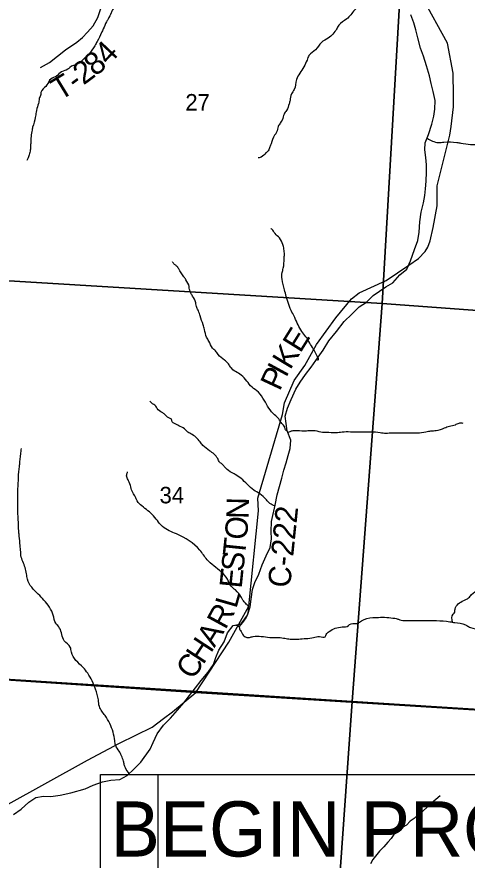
# Model space of a CAD drawing. Extents: x -13.1 to 43.1, y 0 to 22.
# Drawn here: x 3.976 to 5.119, y 16.632 to 18.772 of the extents above; entities that cross this region are included whole.
import ezdxf

# ---------------------------------------------------------------- set-up
doc = ezdxf.new("R2010")
doc.units = 0
for name, color, linetype in [('GM_X_Corporation', 7, 'Continuous'), ('GM_X_County_Road', 7, 'Continuous'), ('GM_X_County_Road_Text', 7, 'Continuous'), ('GM_X_Minor_River', 7, 'Continuous'), ('GM_X_Section_Text', 7, 'Continuous'), ('GM_X_Township_Road', 7, 'Continuous'), ('GM_X_Township_Road_Text', 7, 'Continuous'), ('SH_Masking', 7, 'Continuous'), ('SH_Text', 7, 'Continuous')]:
    doc.layers.add(name, color=color, linetype=linetype)

msp = doc.modelspace()

# ---------------------------------------------------------------- linework, layer by layer
at = {"layer": 'GM_X_Corporation'}
for points in [[(7.0804, 20.9), (2.1, 20.9), (2.1, 17.2152), (2.1437, 17.2135), (2.8442, 17.1637), (3.8328, 17.0966), (4.4304, 17.0575), (6.8234, 16.908), (6.8365, 17.1257), (6.9507, 19.0184), (6.9616, 19.1692), (7.0106, 19.8452), (7.0162, 19.896), (7.0615, 20.6138)], [(3.9684, 19.0905), (4.9602, 19.0234), (4.9031, 18.044), (3.9134, 18.1046)], [(4.9602, 19.0234), (5.9495, 18.9594), (5.8912, 17.9717), (4.9031, 18.044)], [(4.9031, 18.044), (4.8272, 17.0344), (3.8395, 17.0976), (3.9134, 18.1046)], [(4.9031, 18.044), (5.8912, 17.9717), (5.8169, 16.9715), (4.8272, 17.0344)], [(2.1, 17.2152), (2.1, 14.1), (6.619, 14.1), (6.6992, 15.2074), (6.7528, 15.9566), (6.8234, 16.908), (4.4304, 17.0575), (3.8328, 17.0966), (2.8442, 17.1637), (2.1437, 17.2135)], [(3.8395, 17.0976), (4.8272, 17.0344), (4.7589, 16.0643), (3.7693, 16.1222)], [(4.8272, 17.0344), (5.8169, 16.9715), (5.7391, 16.0144), (4.7589, 16.0643)]]:
    msp.add_lwpolyline(points, close=True, dxfattribs=at)
at = {"layer": 'GM_X_County_Road'}
for points in [[(5.0783, 18.4932), (5.0848, 18.5434), (5.0843, 18.5717), (5.0834, 18.6291), (5.0689, 18.7047), (5.0057, 18.8205)], [(4.348, 16.991), (4.3711, 17.0083), (4.4306, 17.0569), (4.5145, 17.185), (4.5648, 17.2761), (4.5898, 17.5185), (4.5882, 17.5504), (4.6501, 17.7629), (4.6558, 17.7923), (4.6802, 17.8489), (4.7075, 17.887), (4.7367, 17.9403), (4.7858, 18.0078), (4.8257, 18.056), (4.8449, 18.0712), (4.9135, 18.1029), (4.9707, 18.1417), (4.996, 18.1588), (5.0124, 18.1761), (5.0195, 18.1874), (5.0253, 18.2031), (5.0327, 18.2373), (5.0429, 18.2924), (5.0432, 18.3425), (5.0754, 18.4715), (5.0783, 18.4932)], [(3.7439, 16.658), (4.1556, 16.8859), (4.2369, 16.929), (4.3192, 16.9696), (4.348, 16.991)]]:
    msp.add_lwpolyline(points, dxfattribs=at)
at = {"layer": 'GM_X_Minor_River'}
for points in [[(4.7413, 17.9083), (4.7535, 17.9256), (4.7681, 17.9498), (4.7872, 17.9731), (4.8071, 17.9988), (4.8262, 18.0176), (4.8453, 18.0356), (4.8635, 18.0476), (4.8803, 18.0649), (4.9131, 18.0867), (4.9306, 18.0971), (4.9481, 18.1167), (4.9664, 18.131), (4.9757, 18.1529), (4.9858, 18.1809), (4.9943, 18.2044), (4.9975, 18.2256), (4.9992, 18.2514), (5.0024, 18.2764), (5.0079, 18.2998), (5.0119, 18.318), (5.0135, 18.3355), (5.0152, 18.3544), (5.0161, 18.3772), (5.0163, 18.3961), (5.0142, 18.4151), (5.0113, 18.4341), (5.0129, 18.4516), (5.0214, 18.4727), (5.0292, 18.4992), (5.0347, 18.5197), (5.0371, 18.5371), (5.038, 18.5591), (5.0329, 18.5819), (5.0278, 18.6024), (5.0234, 18.6222), (5.016, 18.6473), (5.0087, 18.6716), (5.0005, 18.6922), (4.9939, 18.718), (4.9888, 18.7386), (4.9836, 18.7568), (4.9762, 18.7766)], [(3.968, 16.7477), (3.987, 16.7612), (4.0061, 16.7792), (4.0244, 16.7912), (4.0441, 16.7941), (4.0622, 16.7932), (4.0857, 16.7968), (4.113, 16.8026), (4.1494, 16.8129), (4.17, 16.8219), (4.1935, 16.8308), (4.2147, 16.8352), (4.2375, 16.8365), (4.2565, 16.847), (4.274, 16.8635), (4.2908, 16.8808), (4.3145, 16.9132), (4.3223, 16.9306), (4.3323, 16.9526), (4.3484, 16.9744), (4.3659, 16.9917), (4.3835, 17.0121), (4.4003, 17.0309), (4.4141, 17.0498), (4.4294, 17.0694), (4.4439, 17.0875), (4.4615, 17.1086), (4.4753, 17.1282), (4.4815, 17.1463), (4.4892, 17.1645), (4.5022, 17.1856), (4.5108, 17.2083), (4.5253, 17.2272), (4.5458, 17.2315), (4.5618, 17.2534), (4.5681, 17.2746), (4.5705, 17.2943), (4.5745, 17.3186), (4.5799, 17.336), (4.5907, 17.3579), (4.5985, 17.3813), (4.6092, 17.404), (4.6193, 17.4252), (4.6225, 17.4472), (4.6219, 17.4654), (4.6228, 17.4912), (4.6315, 17.5328), (4.637, 17.5586), (4.6425, 17.5798), (4.6487, 17.601), (4.6542, 17.6214), (4.6596, 17.6396), (4.6651, 17.6585), (4.6698, 17.6767), (4.6714, 17.6979), (4.6625, 17.7215), (4.6575, 17.7587), (4.663, 17.7784), (4.6723, 17.8011), (4.6846, 17.8268), (4.6953, 17.8449), (4.7084, 17.8638), (4.7229, 17.8826), (4.7413, 17.9083)], [(5.0502, 16.7954), (5.0394, 16.7854), (5.029, 16.7765), (5.0187, 16.7672), (5.0068, 16.756), (4.996, 16.7475), (4.9849, 16.7378), (4.9746, 16.7304), (4.9653, 16.7203), (4.9543, 16.7148), (4.9443, 16.7051), (4.9332, 16.6966), (4.9262, 16.6869), (4.9174, 16.6772), (4.9077, 16.6656), (4.8966, 16.6548), (4.8796, 16.6338), (4.8737, 16.6229)]]:
    msp.add_lwpolyline(points, dxfattribs=at)
for points in [[(4.8375, 19.0235), (4.8415, 19.0229), (4.8385, 19.0177), (4.8294, 19.0125), (4.815, 19.0097), (4.8105, 19.0105), (4.8034, 19.0155), (4.7981, 19.019), (4.7819, 19.0279), (4.7714, 19.0341), (4.7549, 19.0487), (4.7474, 19.0564), (4.7366, 19.0747), (4.7317, 19.0842), (4.722, 19.1002), (4.7176, 19.1075), (4.7082, 19.1212), (4.703, 19.1285), (4.6902, 19.143), (4.6655, 19.1631), (4.661, 19.1714), (4.652, 19.1814), (4.6291, 19.195), (4.6182, 19.1989), (4.6008, 19.2033), (4.5937, 19.2049), (4.5823, 19.2058), (4.5767, 19.2059), (4.5653, 19.2049), (4.5601, 19.2046), (4.5551, 19.2043), (4.5487, 19.2037), (4.5397, 19.2038), (4.537, 19.2031), (4.5306, 19.2017), (4.5261, 19.2006), (4.5143, 19.1992), (4.5072, 19.199), (4.4939, 19.1965), (4.4886, 19.1947), (4.4818, 19.1891), (4.478, 19.185), (4.4708, 19.1787), (4.4674, 19.1753), (4.4639, 19.172), (4.4552, 19.1615), (4.451, 19.1551), (4.443, 19.1424), (4.4399, 19.1349), (4.4356, 19.1172), (4.4325, 19.1036), (4.4283, 19.0938), (4.418, 19.0724), (4.4054, 19.0545), (4.3996, 19.044), (4.3973, 19.0323), (4.3821, 19.0166), (4.3679, 18.9915), (4.3595, 18.9783), (4.3409, 18.9533), (4.3306, 18.9425), (4.3135, 18.9212), (4.3039, 18.9096), (4.2834, 18.8894), (4.2751, 18.8801), (4.2602, 18.8633), (4.2537, 18.8558), (4.2449, 18.8401), (4.2407, 18.8311), (4.2312, 18.8127), (4.2266, 18.8044), (4.2193, 18.7894), (4.2155, 18.7819), (4.2078, 18.7661), (4.2036, 18.7586), (4.1956, 18.7413), (4.191, 18.7316), (4.1802, 18.7094), (4.1738, 18.6985), (4.1585, 18.6768), (4.1479, 18.6671), (4.1293, 18.6515), (4.1107, 18.6435), (4.1054, 18.6386), (4.0895, 18.6324), (4.0766, 18.6209), (4.0622, 18.6139), (4.0526, 18.5989), (4.0397, 18.5851), (4.037, 18.5776), (4.0362, 18.5723), (4.0339, 18.567), (4.0316, 18.555), (4.0296, 18.5478), (4.025, 18.5294), (4.023, 18.5165), (4.016, 18.492)], [(4.9331, 18.8445), (4.9369, 18.8404), (4.9233, 18.8289), (4.8968, 18.8191), (4.874, 18.8096), (4.8434, 18.7968), (4.8335, 18.7886), (4.8133, 18.7662), (4.7932, 18.7506), (4.7875, 18.7408), (4.7666, 18.7177), (4.7491, 18.7066), (4.7343, 18.6883), (4.7176, 18.6738), (4.7126, 18.6621), (4.6946, 18.6287), (4.6858, 18.6126), (4.68, 18.587), (4.6731, 18.5765), (4.6696, 18.5595), (4.6673, 18.5508), (4.6604, 18.5339), (4.6543, 18.5249), (4.6523, 18.5182), (4.6447, 18.502), (4.6393, 18.4934), (4.6354, 18.4791), (4.6305, 18.4712), (4.6213, 18.4498), (4.6182, 18.4415), (4.614, 18.4317), (4.6083, 18.4265), (4.5965, 18.4157), (4.5912, 18.4143), (4.5886, 18.4143)], [(4.016, 18.492), (4.0141, 18.4811), (4.0117, 18.4641), (4.0113, 18.4562), (4.0112, 18.4505), (4.0108, 18.4407), (4.0104, 18.4358), (4.0096, 18.4305), (4.0068, 18.4188), (4.0049, 18.4139), (4.0015, 18.4068)], [(5.0177, 18.4635), (5.0456, 18.4528), (5.06, 18.4538), (5.0928, 18.4529), (5.1034, 18.4512), (5.1275, 18.4479), (5.1494, 18.4472), (5.1573, 18.444), (5.1715, 18.431), (5.1794, 18.4192), (5.182, 18.4085), (5.1912, 18.3774), (5.2035, 18.3564), (5.2091, 18.3439), (5.227, 18.3194), (5.2378, 18.3026), (5.2412, 18.2908), (5.2515, 18.2586), (5.2567, 18.2384), (5.2645, 18.2262), (5.2775, 18.1984), (5.2861, 18.1817), (5.2887, 18.1714), (5.2956, 18.1452), (5.3001, 18.1308), (5.3008, 18.1229), (5.3043, 18.0876), (5.305, 18.0789), (5.3071, 18.0558), (5.3093, 18.0433), (5.3107, 18.0361), (5.3148, 18.0179), (5.3173, 18.0065), (5.3267, 17.9905), (5.3285, 17.9799), (5.3326, 17.9723), (5.3411, 17.9536), (5.3471, 17.9437), (5.3569, 17.9375), (5.3722, 17.9226), (5.3801, 17.9141), (5.3906, 17.9095), (5.4042, 17.8983), (5.4121, 17.8933), (5.4237, 17.8916), (5.4419, 17.8898), (5.4502, 17.8916), (5.4649, 17.8936), (5.488, 17.8971), (5.4967, 17.9), (5.5069, 17.9017), (5.5194, 17.9088), (5.5285, 17.9166), (5.5463, 17.9224), (5.5769, 17.9355), (5.5868, 17.9362), (5.5913, 17.9372)], [(4.7367, 17.9019), (4.7413, 17.9013), (4.7398, 17.9081), (4.7361, 17.9161), (4.7197, 17.9436), (4.71, 17.96), (4.6995, 17.973), (4.6816, 18.0084), (4.6745, 18.0221), (4.6601, 18.0617), (4.6553, 18.0787), (4.6495, 18.106), (4.6496, 18.1231), (4.6523, 18.1336), (4.6547, 18.1585), (4.6552, 18.1691), (4.6541, 18.1824), (4.6531, 18.1888), (4.6512, 18.1937), (4.6426, 18.2109), (4.6314, 18.2216), (4.6235, 18.2327), (4.6205, 18.2343)], [(4.6625, 17.7215), (4.6581, 17.7236), (4.6563, 17.7308), (4.6488, 17.7396), (4.641, 17.7515), (4.6305, 17.7615), (4.6039, 17.7989), (4.5893, 17.8191), (4.5732, 17.8322), (4.5458, 17.8625), (4.5188, 17.8822), (4.5132, 17.8913), (4.5031, 17.9005), (4.4873, 17.9147), (4.4802, 17.9243), (4.4727, 17.9308), (4.4634, 17.9491), (4.4578, 17.9587), (4.4526, 17.9784), (4.449, 17.9905), (4.4412, 18.0126), (4.4371, 18.0255), (4.433, 18.0339), (4.4301, 18.0464), (4.4223, 18.0631), (4.4197, 18.0673), (4.4163, 18.0738), (4.4156, 18.0769), (4.4145, 18.0799), (4.4134, 18.0871), (4.4052, 18.1046), (4.4, 18.1122), (4.3869, 18.1325), (4.3817, 18.1393), (4.3764, 18.1436), (4.3708, 18.1497)], [(4.631, 17.5306), (4.6183, 17.537), (4.6135, 17.5416), (4.6097, 17.5462), (4.5925, 17.5616), (4.5778, 17.5709), (4.5452, 17.6001), (4.5305, 17.6105), (4.5177, 17.6175), (4.5027, 17.6306), (4.4971, 17.6367), (4.4907, 17.6417), (4.4859, 17.6508), (4.4652, 17.6708), (4.4483, 17.6839), (4.4412, 17.6931), (4.418, 17.7138), (4.4082, 17.7196), (4.4018, 17.7265), (4.3872, 17.7339), (4.383, 17.7366), (4.3706, 17.7444), (4.3688, 17.7501), (4.3616, 17.7539), (4.3511, 17.7635), (4.3451, 17.7674), (4.3323, 17.7778), (4.3305, 17.7816), (4.3207, 17.7897), (4.3136, 17.7966)], [(4.664, 17.7176), (4.6698, 17.7197), (4.6732, 17.7208), (4.6819, 17.7222), (4.7049, 17.7211), (4.7178, 17.722), (4.7329, 17.7218), (4.7521, 17.7178), (4.7615, 17.7176), (4.7861, 17.7169), (4.8016, 17.7186), (4.8227, 17.719), (4.8593, 17.7185), (4.874, 17.719), (4.8982, 17.7172), (4.9057, 17.7159), (4.9208, 17.7157), (4.9454, 17.7158), (4.9574, 17.716), (4.9888, 17.7163), (4.9926, 17.7162), (5.0145, 17.7189), (5.0273, 17.721), (5.0402, 17.722), (5.0617, 17.7285), (5.0742, 17.7332), (5.0893, 17.7368), (5.0984, 17.7408), (5.1082, 17.741)], [(4.2611, 16.8513), (4.2516, 16.8658), (4.2487, 16.8738), (4.2469, 16.8832), (4.2417, 16.8969), (4.2357, 16.9083), (4.2268, 16.9232), (4.2246, 16.935), (4.2202, 16.9566), (4.2001, 16.9985), (4.1855, 17.0217), (4.183, 17.0384), (4.176, 17.0654), (4.1559, 17.1061), (4.1443, 17.1206), (4.1144, 17.1596), (4.1118, 17.1725), (4.0965, 17.1883), (4.0846, 17.2209), (4.0749, 17.2328), (4.0686, 17.2533), (4.0447, 17.2918), (4.0305, 17.3068), (4.0028, 17.3446), (4.0006, 17.3586), (3.9914, 17.3894), (3.9866, 17.4046), (3.9859, 17.4144), (3.9845, 17.43), (3.9824, 17.4542), (3.9813, 17.464), (3.9803, 17.4811), (3.979, 17.511), (3.9787, 17.5215), (3.9785, 17.5367), (3.9787, 17.5749), (3.98, 17.5941), (3.98, 17.6028), (3.9829, 17.6308), (3.9837, 17.6425), (3.9869, 17.6704), (3.9877, 17.6761)], [(5.0816, 17.2356), (5.0834, 17.2559), (5.0864, 17.2589), (5.0884, 17.2687), (5.1104, 17.2907), (5.1229, 17.2973), (5.1305, 17.3059), (5.1483, 17.3185), (5.1559, 17.3229), (5.1707, 17.3371), (5.1818, 17.3456), (5.1932, 17.3636), (5.2274, 17.3922), (5.2418, 17.4019), (5.2513, 17.4161), (5.2786, 17.4338), (5.2919, 17.4405), (5.3029, 17.4524), (5.3355, 17.4724), (5.3511, 17.4793), (5.3715, 17.493), (5.3768, 17.4967), (5.3818, 17.4997), (5.3951, 17.5135), (5.4049, 17.5202), (5.4136, 17.5242), (5.419, 17.5279), (5.4246, 17.5282), (5.4284, 17.5338), (5.4455, 17.5385), (5.4651, 17.545), (5.4708, 17.548), (5.4852, 17.5508), (5.4882, 17.5534), (5.5117, 17.5598), (5.5336, 17.5648), (5.5416, 17.5689), (5.5514, 17.5755), (5.5753, 17.5858), (5.5825, 17.588), (5.587, 17.5894), (5.5908, 17.5969), (5.5985, 17.6085), (5.6117, 17.6182), (5.6213, 17.632), (5.6357, 17.639)], [(4.5403, 17.2239), (4.5644, 17.2723), (4.5633, 17.2765), (4.5603, 17.2796), (4.5569, 17.2838), (4.5498, 17.2915), (4.5461, 17.2979), (4.5307, 17.3174), (4.5202, 17.3274), (4.5105, 17.345), (4.476, 17.3783), (4.4592, 17.3941), (4.4408, 17.4185), (4.3811, 17.4595), (4.3461, 17.4781), (4.336, 17.4892), (4.3229, 17.5053), (4.2933, 17.5307), (4.2816, 17.5433), (4.2783, 17.5509), (4.2671, 17.5715), (4.2657, 17.5787), (4.2597, 17.5947), (4.2571, 17.5996), (4.2549, 17.6095), (4.2565, 17.614), (4.2569, 17.617)], [(4.5307, 17.2283), (4.5403, 17.2239), (4.541, 17.2213), (4.5425, 17.2163), (4.5455, 17.2121), (4.5485, 17.2056), (4.5582, 17.1976), (4.5665, 17.1971), (4.5756, 17.1992), (4.6179, 17.1971), (4.6533, 17.1955), (4.6597, 17.1942), (4.6737, 17.1925), (4.7096, 17.1943), (4.7292, 17.1966), (4.744, 17.1991), (4.7591, 17.1989), (4.7614, 17.2045), (4.769, 17.2123), (4.8019, 17.2236), (4.8178, 17.2271), (4.8204, 17.2298), (4.8389, 17.2325), (4.8458, 17.2358), (4.8511, 17.2391), (4.8794, 17.2474), (4.8991, 17.2483), (4.9017, 17.2486), (4.9097, 17.2485), (4.9304, 17.246), (4.9413, 17.2443), (4.9481, 17.2415), (4.9632, 17.2398), (4.976, 17.24), (5.0089, 17.2403), (5.0417, 17.2398), (5.0753, 17.2367), (5.0874, 17.2346), (5.1149, 17.2293), (5.1186, 17.227), (5.1273, 17.2224), (5.151, 17.2118), (5.154, 17.2065), (5.1619, 17.1977), (5.1863, 17.1829), (5.1998, 17.1771), (5.2096, 17.1682), (5.2404, 17.1531), (5.2604, 17.1456), (5.2641, 17.1406), (5.2743, 17.1337), (5.3029, 17.1212), (5.3149, 17.1168), (5.3224, 17.1099), (5.3435, 17.1002), (5.3544, 17.0947), (5.3563, 17.0913), (5.3611, 17.0848), (5.3702, 17.0794), (5.3905, 17.0647), (5.4028, 17.0502), (5.4163, 17.0424), (5.4186, 17.0375), (5.4249, 17.0287), (5.4411, 17.0152), (5.4475, 17.0102), (5.4579, 16.9972), (5.4632, 16.9915), (5.4744, 16.9769), (5.48, 16.9708), (5.4845, 16.9624), (5.4972, 16.9482), (5.5066, 16.9424), (5.5111, 16.9382), (5.5138, 16.9389), (5.5206, 16.9396), (5.5583, 16.939), (5.5806, 16.9368), (5.6439, 16.925), (5.6594, 16.9187), (5.6792, 16.9022), (5.6879, 16.8952), (5.7032, 16.8788), (5.7108, 16.8718), (5.722, 16.8573), (5.7269, 16.8535), (5.7306, 16.8519)]]:
    msp.add_spline(points, degree=3, dxfattribs=at)
at = {"layer": 'GM_X_Township_Road'}
msp.add_lwpolyline([(4.0363, 18.6432), (4.0593, 18.6562), (4.1, 18.6879), (4.1283, 18.7073), (4.1425, 18.7189), (4.1556, 18.7331), (4.1699, 18.7489), (4.1819, 18.77), (4.1986, 18.821), (4.2183, 18.9023), (4.2288, 18.9755), (4.2316, 18.9861), (4.2344, 18.9971), (4.2418, 19.0091), (4.256, 19.0218), (4.2878, 19.0461), (4.3313, 19.0876), (4.3421, 19.0978)], dxfattribs=at)
at = {"layer": 'SH_Masking'}
msp.add_lwpolyline([(4.3351, 16.8489), (5.841, 16.8489), (5.841, 16.3645), (4.3351, 16.3645)], close=True, dxfattribs=at)
at = {"layer": 'SH_Text'}
msp.add_lwpolyline([(4.1884, 16.8489), (5.841, 16.8489), (5.841, 16.3645), (4.1884, 16.3645)], close=True, dxfattribs=at)

# ---------------------------------------------------------------- texts
at = {"layer": 'GM_X_County_Road_Text'}
for s, height, rotation, p in [('E', 0.0568, 58.1241, (4.6956, 17.9166)), ('K', 0.0568, 58.9175, (4.6699, 17.874)), ('I', 0.0568, 61.4132, (4.659, 17.8541)), ('P', 0.0568, 65.0012, (4.6433, 17.8201)), ('N', 0.0568, 88.6994, (4.5645, 17.4973)), ('C-222', 0.05682, 84.2083, (4.6695, 17.3214)), ('O', 0.0568, 84.3174, (4.5593, 17.4429)), ('T', 0.0568, 84.1184, (4.5549, 17.4004)), ('S', 0.0568, 84.1188, (4.551, 17.3622)), ('E', 0.0568, 84.1118, (4.5466, 17.32)), ('L', 0.0568, 74.1074, (4.533, 17.2685)), ('R', 0.0568, 61.4343, (4.5055, 17.2148)), ('A', 0.0568, 58.4021, (4.4776, 17.1694)), ('H', 0.0568, 56.7069, (4.4492, 17.126)), ('C', 0.0568, 56.6065, (4.4234, 17.087))]:
    msp.add_text(s, height=height, rotation=rotation, dxfattribs=at).set_placement(p)
at = {"layer": 'GM_X_Section_Text'}
for s, p in [('27', (4.4038, 18.5339)), ('34', (4.3384, 17.5372))]:
    msp.add_text(s, height=0.04186, rotation=0, dxfattribs=at).set_placement(p)
at = {"layer": 'GM_X_Township_Road_Text'}
for s, rotation, p in [('4', 46.5265, (4.2088, 18.6467)), ('8', 38.0918, (4.1746, 18.619)), ('2', 36.6755, (4.1453, 18.5971)), ('T', 31.4312, (4.0855, 18.5579)), ('-', 36.4542, (4.1263, 18.5831))]:
    msp.add_text(s, height=0.0568, rotation=rotation, dxfattribs=at).set_placement(p)
at = {"layer": 'SH_Text'}
msp.add_text('BEGIN PROJECT', height=0.14, dxfattribs=at).set_placement((4.2143, 16.641))

doc.saveas('drawing.dxf')
